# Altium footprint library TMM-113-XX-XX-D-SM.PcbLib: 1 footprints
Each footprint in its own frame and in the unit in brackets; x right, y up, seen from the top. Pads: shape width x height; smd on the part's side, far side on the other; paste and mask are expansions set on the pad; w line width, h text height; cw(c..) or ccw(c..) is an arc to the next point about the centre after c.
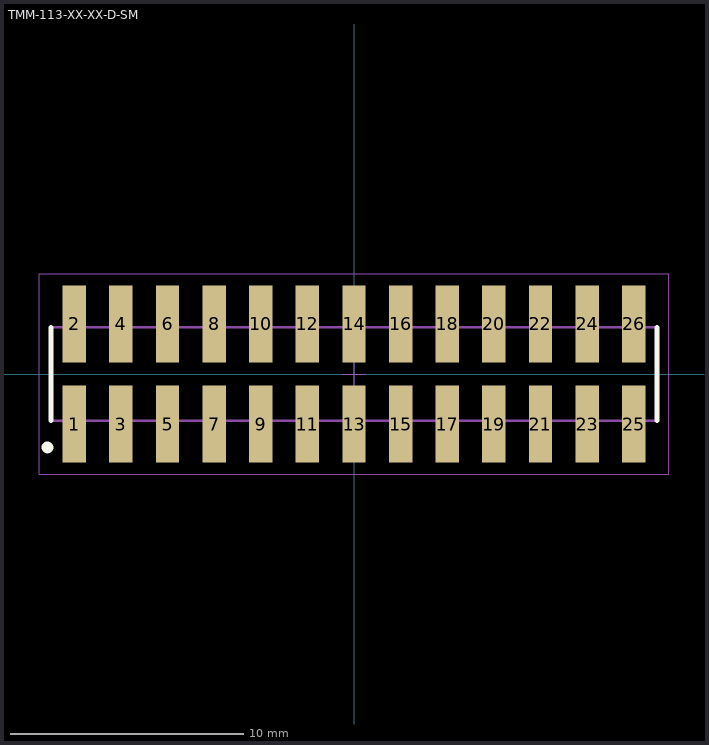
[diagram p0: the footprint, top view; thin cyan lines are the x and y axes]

## TMM-113-XX-XX-D-SM [mm] "2.00mm pitch, 26 pin, terminal strip; double row, SMT"
height 2.77
pads (26):
  rect 1x3.3 smd mask+0: 1(-12,-2.15) 2(-12,2.15) 3(-10,-2.15) 4(-10,2.15) 5(-8,-2.15) 6(-8,2.15) 7(-6,-2.15) 8(-6,2.15) 9(-4,-2.15) 10(-4,2.15) 11(-2,-2.15) 12(-2,2.15) 13(0,-2.15) 14(0,2.15) 15(2,-2.15) 16(2,2.15) 17(4,-2.15) 18(4,2.15) 19(6,-2.15) 20(6,2.15) 21(8,-2.15) 22(8,2.15) 23(10,-2.15) 24(10,2.15) 25(12,-2.15) 26(12,2.15)
Top Overlay:
  circle w0.25: c-13.15,-3.15 r0.125
  lines w0.2: -13,-2 -13,2 ; 13,-2 13,2
Mechanical 12:
  lines w0.001: -13,-2 13,-2 13,2 -13,2 -13,-2
Mechanical 13:
  lines w0.1: -13,-2 13,-2 13,2 -13,2 -13,-2
  text ".Designator" at 0,-0.127 h1.52
Mechanical 15:
  lines w0.05: -0.5,0 0.5,0 ; 0,-0.5 0,0.5 ; -13.5,-4.3 13.5,-4.3 13.5,4.3 -13.5,4.3 -13.5,-4.3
